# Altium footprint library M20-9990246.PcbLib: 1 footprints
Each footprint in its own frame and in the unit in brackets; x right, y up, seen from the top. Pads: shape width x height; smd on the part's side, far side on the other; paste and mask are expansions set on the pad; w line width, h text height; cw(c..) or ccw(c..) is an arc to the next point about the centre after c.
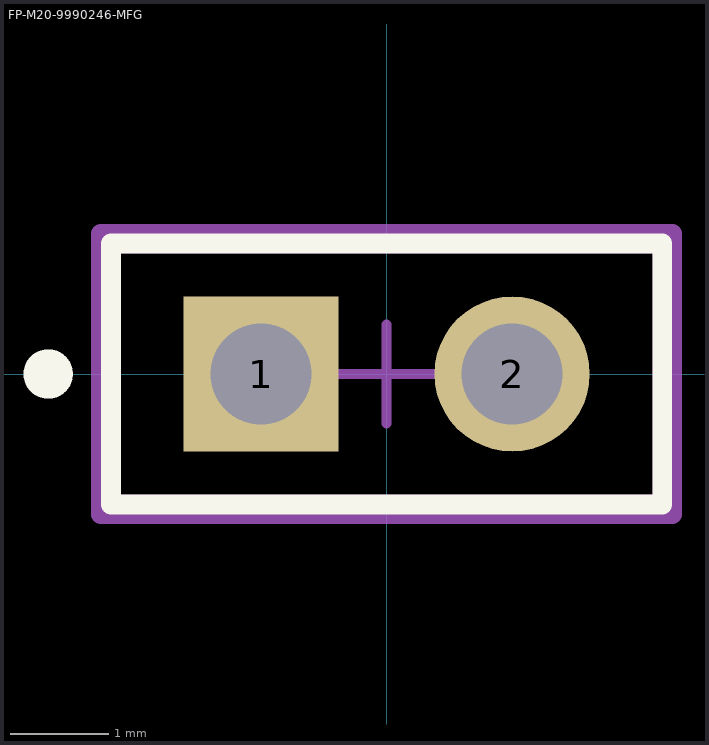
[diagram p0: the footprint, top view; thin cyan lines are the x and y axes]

## FP-M20-9990246-MFG [mm]
pads (2):
  rect 1.57x1.57 hole 1.02 paste-1000 mask+0: 1(-1.27,0)
  round 1.57 hole 1.02 paste-1000 mask+0: 2(1.27,0)
Top Overlay:
  circle w0.25: c-3.425,0 r0.125
  lines w0.2: -2.79,-1.32 2.79,-1.32 2.79,1.32 -2.79,1.32 -2.79,-1.32
Mechanical 5:
  lines w0.2: -2.89,-1.42 2.89,-1.42 2.89,1.42 -2.89,1.42 -2.89,-1.42
  text ".Designator" at 0,0.188 h1
Mechanical 13:
  lines w0.2: -2.79,-1.32 2.79,-1.32 2.79,1.32 -2.79,1.32 -2.79,-1.32
Mechanical 15:
  lines w0.2: -2.89,-1.42 2.89,-1.42 2.89,1.42 -2.89,1.42 -2.89,-1.42
Mechanical 16:
  lines w0.1: -0.5,0 0.5,0 ; 0,-0.5 0,0.5
3D body "Conn_Harwin_M20-9990246_eec.STEP": height 0.25, standoff 0, extent -2.89,-1.42 2.89,1.42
